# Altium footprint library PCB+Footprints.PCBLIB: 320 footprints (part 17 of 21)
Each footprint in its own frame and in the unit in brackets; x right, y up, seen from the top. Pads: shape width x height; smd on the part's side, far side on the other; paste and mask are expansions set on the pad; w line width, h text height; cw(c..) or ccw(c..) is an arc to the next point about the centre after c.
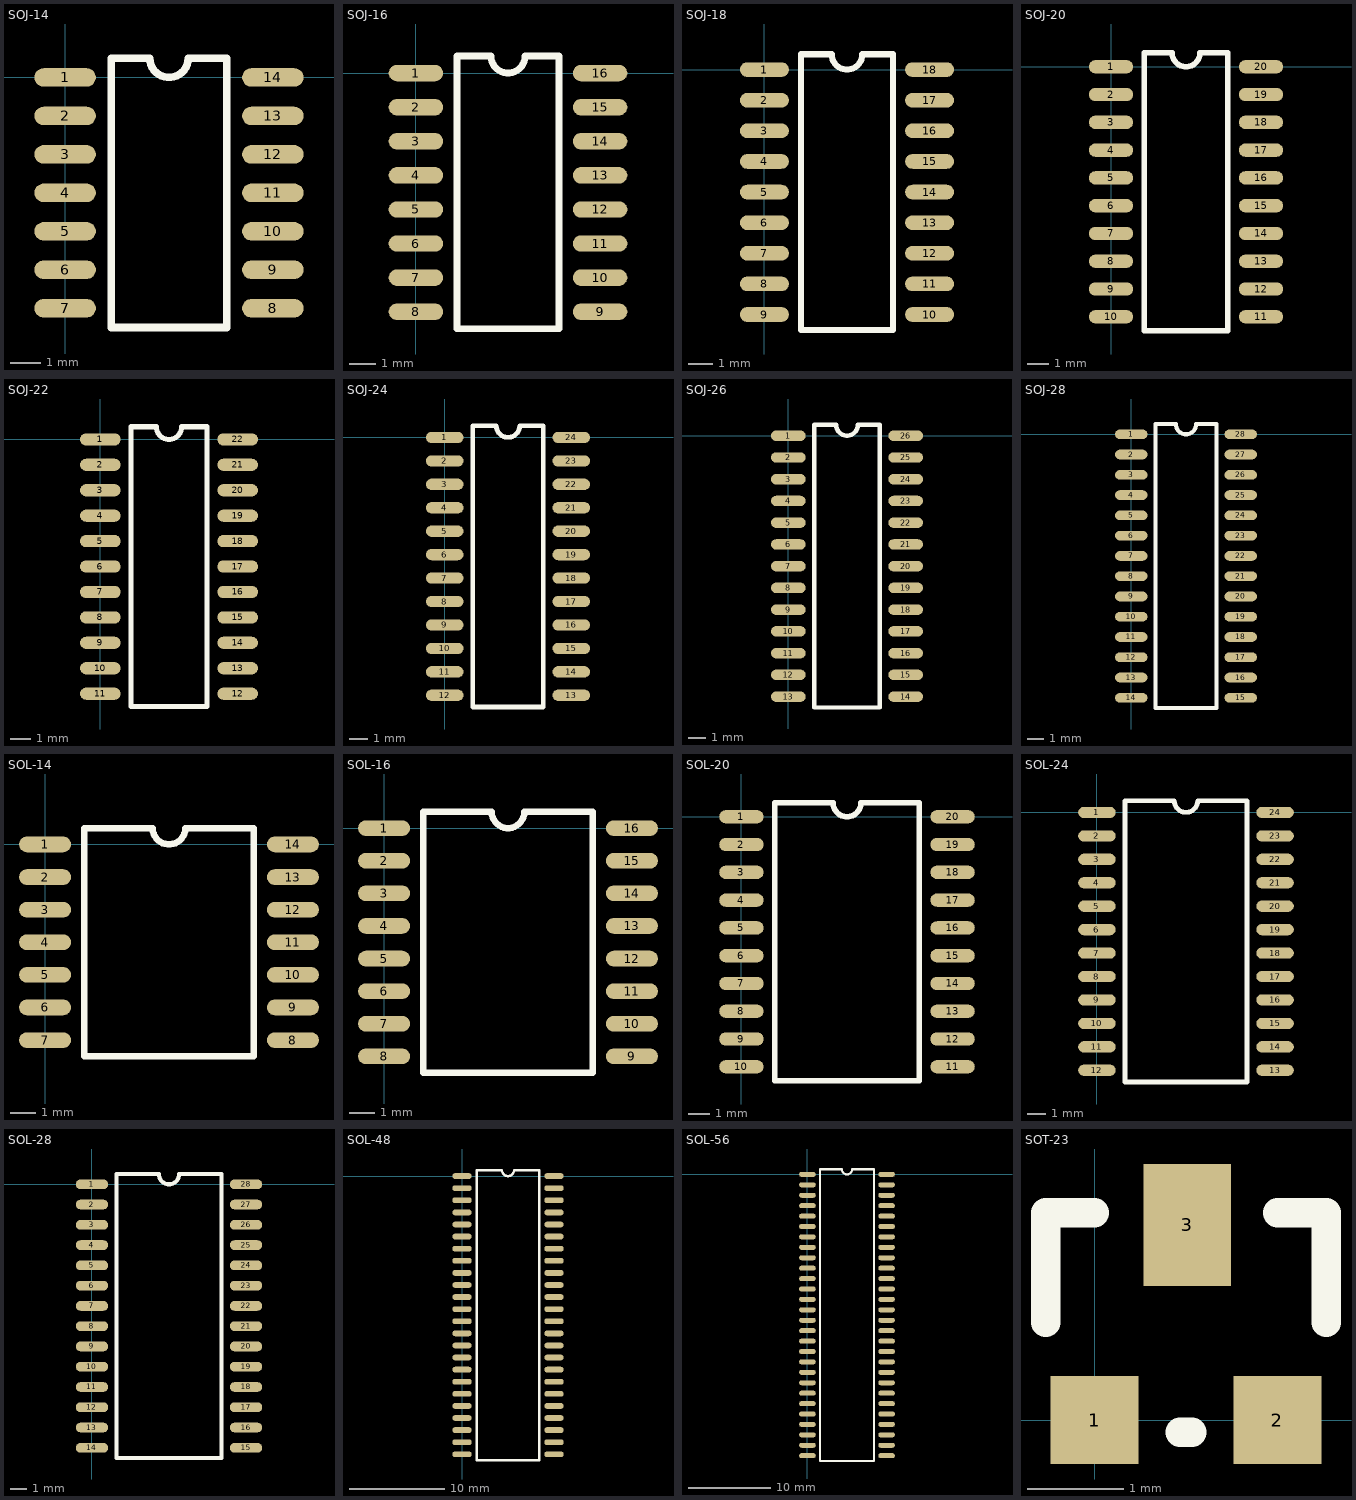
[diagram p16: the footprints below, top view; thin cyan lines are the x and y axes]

## SOJ-14 [mil]
pads (14):
  oval 80x24 smd: 1(0,0) 2(0,-50) 3(0,-100) 4(0,-150) 5(0,-200) 6(0,-250) 7(0,-300) 8(270,-300) 9(270,-250) 10(270,-200) 11(270,-150) 12(270,-100) 13(270,-50) 14(270,0)
TopOverlay:
  lines w10: 60,25 60,25 ; 60,25 60,-325 210,-325 210,25 160,25 cw(c135,25) 110,25 60,25

## SOJ-16 [mil]
pads (16):
  oval 80x24 smd: 1(0,0) 2(0,-50) 3(0,-100) 4(0,-150) 5(0,-200) 6(0,-250) 7(0,-300) 8(0,-350) 9(270,-350) 10(270,-300) 11(270,-250) 12(270,-200) 13(270,-150) 14(270,-100) 15(270,-50) 16(270,0)
TopOverlay:
  lines w10: 60,25 60,25 ; 60,25 60,-375 210,-375 210,25 160,25 cw(c135,25) 110,25 60,25

## SOJ-18 [mil]
pads (18):
  oval 80x24 smd: 1(0,0) 2(0,-50) 3(0,-100) 4(0,-150) 5(0,-200) 6(0,-250) 7(0,-300) 8(0,-350) 9(0,-400) 10(270,-400) 11(270,-350) 12(270,-300) 13(270,-250) 14(270,-200) 15(270,-150) 16(270,-100) 17(270,-50) 18(270,0)
TopOverlay:
  lines w10: 60,25 60,25 ; 60,25 60,-425 210,-425 210,25 160,25 cw(c135,25) 110,25 60,25

## SOJ-20 [mil]
pads (20):
  oval 80x24 smd: 1(0,0) 2(0,-50) 3(0,-100) 4(0,-150) 5(0,-200) 6(0,-250) 7(0,-300) 8(0,-350) 9(0,-400) 10(0,-450) 11(270,-450) 12(270,-400) 13(270,-350) 14(270,-300) 15(270,-250) 16(270,-200) 17(270,-150) 18(270,-100) 19(270,-50) 20(270,0)
TopOverlay:
  lines w10: 60,-475 210,-475 210,25 160,25 cw(c135,25) 110,25 60,25 60,-475

## SOJ-22 [mil]
pads (22):
  oval 80x24 smd: 1(0,0) 2(0,-50) 3(0,-100) 4(0,-150) 5(0,-200) 6(0,-250) 7(0,-300) 8(0,-350) 9(0,-400) 10(0,-450) 11(0,-500) 12(270,-500) 13(270,-450) 14(270,-400) 15(270,-350) 16(270,-300) 17(270,-250) 18(270,-200) 19(270,-150) 20(270,-100) 21(270,-50) 22(270,0)
TopOverlay:
  lines w10: 60,-525 210,-525 210,25 160,25 cw(c135,25) 110,25 60,25 60,-525

## SOJ-24 [mil]
pads (24):
  oval 80x24 smd: 1(0,0) 2(0,-50) 3(0,-100) 4(0,-150) 5(0,-200) 6(0,-250) 7(0,-300) 8(0,-350) 9(0,-400) 10(0,-450) 11(0,-500) 12(0,-550) 13(270,-550) 14(270,-500) 15(270,-450) 16(270,-400) 17(270,-350) 18(270,-300) 19(270,-250) 20(270,-200) 21(270,-150) 22(270,-100) 23(270,-50) 24(270,0)
TopOverlay:
  lines w10: 60,25 60,25 ; 60,25 60,-575 210,-575 210,25 160,25 cw(c135,25) 110,25 60,25

## SOJ-26 [mil]
pads (26):
  oval 80x24 smd: 1(0,0) 2(0,-50) 3(0,-100) 4(0,-150) 5(0,-200) 6(0,-250) 7(0,-300) 8(0,-350) 9(0,-400) 10(0,-450) 11(0,-500) 12(0,-550) 13(0,-600) 14(270,-600) 15(270,-550) 16(270,-500) 17(270,-450) 18(270,-400) 19(270,-350) 20(270,-300) 21(270,-250) 22(270,-200) 23(270,-150) 24(270,-100) 25(270,-50) 26(270,0)
TopOverlay:
  lines w10: 60,-625 210,-625 210,25 160,25 cw(c135,25) 110,25 60,25 60,-625

## SOJ-28 [mil]
pads (28):
  oval 80x24 smd: 1(0,0) 2(0,-50) 3(0,-100) 4(0,-150) 5(0,-200) 6(0,-250) 7(0,-300) 8(0,-350) 9(0,-400) 10(0,-450) 11(0,-500) 12(0,-550) 13(0,-600) 14(0,-650) 15(270,-650) 16(270,-600) 17(270,-550) 18(270,-500) 19(270,-450) 20(270,-400) 21(270,-350) 22(270,-300) 23(270,-250) 24(270,-200) 25(270,-150) 26(270,-100) 27(270,-50) 28(270,0)
TopOverlay:
  lines w10: 60,25 60,25 ; 60,25 60,-675 210,-675 210,25 160,25 cw(c135,25) 110,25 60,25

## SOL-14 [mil]
pads (14):
  oval 80x24 smd: 1(0,0) 2(0,-50) 3(0,-100) 4(0,-150) 5(0,-200) 6(0,-250) 7(0,-300) 8(380,-300) 9(380,-250) 10(380,-200) 11(380,-150) 12(380,-100) 13(380,-50) 14(380,0)
TopOverlay:
  lines w10: 60,25 60,25 ; 60,25 60,-325 320,-325 320,25 215,25 cw(c190,25) 165,25 60,25

## SOL-16 [mil]
pads (16):
  oval 80x24 smd: 1(0,0) 2(0,-50) 3(0,-100) 4(0,-150) 5(0,-200) 6(0,-250) 7(0,-300) 8(0,-350) 9(380,-350) 10(380,-300) 11(380,-250) 12(380,-200) 13(380,-150) 14(380,-100) 15(380,-50) 16(380,0)
TopOverlay:
  lines w10: 60,-375 320,-375 320,25 215,25 cw(c190,25) 165,25 60,25 60,-375

## SOL-20 [mil]
pads (20):
  oval 80x24 smd: 1(0,0) 2(0,-50) 3(0,-100) 4(0,-150) 5(0,-200) 6(0,-250) 7(0,-300) 8(0,-350) 9(0,-400) 10(0,-450) 11(380,-450) 12(380,-400) 13(380,-350) 14(380,-300) 15(380,-250) 16(380,-200) 17(380,-150) 18(380,-100) 19(380,-50) 20(380,0)
TopOverlay:
  lines w10: 60,25 60,25 ; 60,25 60,-475 320,-475 320,25 215,25 cw(c190,25) 165,25 60,25

## SOL-24 [mil]
pads (24):
  oval 80x24 smd: 1(0,0) 2(0,-50) 3(0,-100) 4(0,-150) 5(0,-200) 6(0,-250) 7(0,-300) 8(0,-350) 9(0,-400) 10(0,-450) 11(0,-500) 12(0,-550) 13(380,-550) 14(380,-500) 15(380,-450) 16(380,-400) 17(380,-350) 18(380,-300) 19(380,-250) 20(380,-200) 21(380,-150) 22(380,-100) 23(380,-50) 24(380,0)
TopOverlay:
  lines w10: 60,25 60,25 ; 60,25 60,-575 320,-575 320,25 215,25 cw(c190,25) 165,25 60,25

## SOL-28 [mil]
pads (28):
  oval 80x24 smd: 1(0,0) 2(0,-50) 3(0,-100) 4(0,-150) 5(0,-200) 6(0,-250) 7(0,-300) 8(0,-350) 9(0,-400) 10(0,-450) 11(0,-500) 12(0,-550) 13(0,-600) 14(0,-650) 15(380,-650) 16(380,-600) 17(380,-550) 18(380,-500) 19(380,-450) 20(380,-400) 21(380,-350) 22(380,-300) 23(380,-250) 24(380,-200) 25(380,-150) 26(380,-100) 27(380,-50) 28(380,0)
TopOverlay:
  lines w10: 60,25 60,25 ; 60,25 60,-675 320,-675 320,25 215,25 cw(c190,25) 165,25 60,25

## SOL-48 [mil]
pads (48):
  oval 80x24 smd: 1(0,0) 2(0,-50) 3(0,-100) 4(0,-150) 5(0,-200) 6(0,-250) 7(0,-300) 8(0,-350) 9(0,-400) 10(0,-450) 11(0,-500) 12(0,-550) 13(0,-600) 14(0,-650) 15(0,-700) 16(0,-750) 17(0,-800) 18(0,-850) 19(0,-900) 20(0,-950) 21(0,-1000) 22(0,-1050) 23(0,-1100) 24(0,-1150) 25(380,-1150) 26(380,-1100) 27(380,-1050) 28(380,-1000) 29(380,-950) 30(380,-900) 31(380,-850) 32(380,-800) 33(380,-750) 34(380,-700) 35(380,-650) 36(380,-600) 37(380,-550) 38(380,-500) 39(380,-450) 40(380,-400) 41(380,-350) 42(380,-300) 43(380,-250) 44(380,-200) 45(380,-150) 46(380,-100) 47(380,-50) 48(380,0)
TopOverlay:
  lines w10: 60,25 60,25 ; 60,25 60,-1175 320,-1175 320,25 215,25 cw(c190,25) 165,25 60,25

## SOL-56 [mil]
pads (56):
  oval 80x24 smd: 1(0,0) 2(0,-50) 3(0,-100) 4(0,-150) 5(0,-200) 6(0,-250) 7(0,-300) 8(0,-350) 9(0,-400) 10(0,-450) 11(0,-500) 12(0,-550) 13(0,-600) 14(0,-650) 15(0,-700) 16(0,-750) 17(0,-800) 18(0,-850) 19(0,-900) 20(0,-950) 21(0,-1000) 22(0,-1050) 23(0,-1100) 24(0,-1150) 25(0,-1200) 26(0,-1250) 27(0,-1300) 28(0,-1350) 29(380,-1350) 30(380,-1300) 31(380,-1250) 32(380,-1200) 33(380,-1150) 34(380,-1100) 35(380,-1050) 36(380,-1000) 37(380,-950) 38(380,-900) 39(380,-850) 40(380,-800) 41(380,-750) 42(380,-700) 43(380,-650) 44(380,-600) 45(380,-550) 46(380,-500) 47(380,-450) 48(380,-400) 49(380,-350) 50(380,-300) 51(380,-250) 52(380,-200) 53(380,-150) 54(380,-100) 55(380,-50) 56(380,0)
TopOverlay:
  lines w10: 60,25 60,25 ; 60,25 60,-1375 320,-1375 320,25 215,25 cw(c190,25) 165,25 60,25

## SOT-23 [mil]
pads (3):
  rect 36x36 smd: 1(0,0) 2(75,0)
  rect 36x50 smd: 3(38,80)
TopOverlay:
  lines w12: -20,40 -20,85 0,85 ; 35,-5 40,-5 ; 75,85 95,85 95,40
